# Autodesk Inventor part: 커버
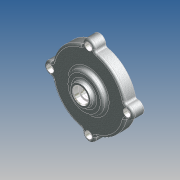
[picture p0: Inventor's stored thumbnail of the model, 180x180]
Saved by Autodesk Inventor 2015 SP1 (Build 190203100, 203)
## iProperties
Created: 2012-05
Part Number: 커버
Document SubType Name: 모델링
Designer: SeoGD™
Material: 일반
Appearance: 알루미늄 캐스트
Mass: 72.5671 g
Surface Area: 278.607 cm^2
Volume: 72.5671 cm^3
Density: 1 g/cm^3
변환 표준: STEP AP214IS
파일 이름: C:\Users\SeoGD\Desktop\?쒗뿕\而ㅻ쾭-1.stp
전처리기: Build: 253, Release: 2010 SP1 - Date: Wed 07/29/2009
전송 단위: 밀리미터
불확실성: 0.01
Author: SeoGD™
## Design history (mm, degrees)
sketch "스케치1"
  geometry: L1 (0, 0)-(0, 26); L2 (50, 0)-(50, 15); L3 (50, 15)-(25, 15); L4 (25, 15)-(25, 21); L5 (25, 21)-(15, 21); L6 (15, 21)-(13.66, 26); L7 (13.66, 26)-(10, 26); L8 (50, 0)-(45, 0); L9 (45, 0)-(45, 10); L10 (45, 10)-(14.5, 10); L11 (14.5, 10)-(13.266, 3); L12 (13.266, 3)-(11, 3); L13 (11, 3)-(11, 16); L14 (11, 16)-(7.5, 16); L15 (7.5, 16)-(7.5, 19); L16 (7.5, 19)-(10, 19); L17 (10, 19)-(10, 26)
  constraints: 34 end point, 10 parallel, 2 perpendicular, 2 point on line, 1 vertical
  dimensions: "d11" = 100 diameter of L2 L1; "d12" = 22 diameter of L13 L1; "d13" = 90 diameter of L9 L1; "d14" = 15 distance between parallel lines of L3 L8; "d15" = 10 distance between parallel lines of L8 L10; "d16" = 29 diameter of L10.end L1; "d17" = 100 deg angle of L11 L10; "d18" = 7 distance between parallel lines of L12 L10; "d19" = 13 distance between parallel lines of L14 L12; "d20" = 3 distance between parallel lines of L16 L14; "d21" = 15 diameter of L15 L1; "d22" = 20 diameter of L17 L1; "d23" = 30 diameter of L5.end L1; "d24" = 6 distance between parallel lines of L5 L3; "d25" = 50 diameter of L4 L1; "d26" = 105 deg angle of L5 L6; "d50" = 26 distance of L1.start L1.end
revolve "회전1" sketch "스케치1" stored, may be unused: angle "d27" = 90 deg
sketch "스케치2" dims "d29" = 104
  geometry: A1 r 8.5 centre (0, 52) between (8.074, 49.344) and (-8.074, 49.344); A2 r 50 centre (0, 0) between (-8.074, 49.344) and (8.074, 49.344) reference; 2 further points
  constraints: 4 point on circle, 2 vertical alignment, 1 centre point, 1 coincident, 2 other
  dimensions: "d28" = 17 diameter of A1
extrude "돌출1" join sketch "스케치2" stored distance "d30" = 10; taper "d31" = 0 deg
fillet "모깎기3" dims "d32" = 3
fillet "모깎기4" dims "d45" = 3, "d46" = 0.2
chamfer "모따기1" distance "d47" = 1; stored, may be unused: second distance "d48" = 2, angle "d49" = 45 deg
hole "구멍2" diameter "d38" = 5.5; stored, may be unused: countersink angle "d42" = 90 deg, drill point angle "d44" = 118 deg; dims "d36" = 10, "d37" = 10, "d39" = 6, "d40" = 9.5, "d41" = 5.4, "d43" = 8
node "솔리드1"
node "솔리드 본체"
node "곡면 본체"
pattern_circular "원형 패턴1" dims angle "d34" = 360 deg
pattern_circular "원형 패턴2" dims angle "d52" = 360 deg
node "솔리드2"
